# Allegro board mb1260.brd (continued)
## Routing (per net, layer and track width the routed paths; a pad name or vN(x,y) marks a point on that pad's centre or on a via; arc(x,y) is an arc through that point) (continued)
5V: length 96.6
  TOP w0.508: CN8.4 77.71,42.19 ; CN8.4 v4(80.09,41.35) ; CN8.4 77.71,40.51 ; 65.79,66.32 C17.2 ; C17.2 65.79,67.54 ; C17.2 65.14,66.93 ; P1.15 74.64,70.5 ; P1.15 73.77,71.36 ; P1.15 72.91,70.5 ; P1.15 73.77,69.64 ; 70.91,72.5 P1.6 ; P1.6 71.77,73.36 ; P1.6 72.64,72.5 ; P1.6 71.77,71.64 ; L3.1 v4(20.19,27.56) 17.17,30.58 CN12.5 ; 64.76,67.14 U4.6 64.32,66.59 ; 77.71,35.43 CN8.8 ; CN8.8 77.71,37.11 ; CN8.8 v4(80.09,36.27) ; 64.32,70.57 U4.1 64.76,70.02 ; 42.42,93.6 v4(42.42,94.61) ; CN8.10 77.71,34.57 ; CN8.10 77.71,32.89 ; CN8.10 v4(80.09,33.73) ; v4(44.43,94.72) 44.81,94.34 D1.1 ; CN8.6 77.71,39.65 ; CN8.6 v4(80.09,38.81) ; CN8.6 77.71,37.97 ; 65.43,69.47 65.91,69.47 ; 65.91,69.47 65.91,68.99 ; 65.91,69.47 65.91,69.95 ; CN8.2 v4(80.01,43.89) ; CN8.2 77.71,43.05 ; CN8.2 77.71,44.73 ; v4(36.13,13.36) U13.5 ; U14.5 v4(58.11,13.51)
  L4_SIG w0.508: P1.6 72.64,72.5 ; P1.6 71.77,71.64 ; P1.6 71.77,73.36 ; P1.6 70.91,72.5 ; 73.77,69.64 P1.15 ; P1.15 73.77,71.36 ; P1.15 74.64,70.5 ; P1.15 72.91,70.5
  BOTTOM w0.508: v4(42.42,94.61) 42.53,94.72 v4(44.43,94.72) 45.48,94.72 46.23,93.98 46.23,79.88 50.42,75.69 50.42,73.03 52.7,70.74 55.88,70.74 56.9,69.72 58.29,69.72 58.93,70.36 64.64,70.36 65.53,69.47 v4(65.53,68.71)
  vias: v4(65.53,67.94) v4(66.29,68.71) v4(66.29,67.94) v4(79.32,45.85) v4(79.35,45.01)
5V_ST_LINK: length 44.4
  TOP w0.508: U1.7 64.9,78.74 ; U1.6 C5.2 ; C5.2 65.41,76.99 ; C5.2 65.41,77.95 ; SB3.2 65.5,79.28
  TOP w1.016: CN8.1 70.79,43.89 69.88,44.81 69.88,76.43 67.56,78.74 66.42,78.74
5V_USB_FS: length 42.4
  TOP w0.508: D3.1 70.16,36.2 ; D3.1 68.94,36.2 ; D3.1 69.55,36.81 ; D3.1 69.55,35.58
  L4_SIG w1.016: 68.84,34.22 66.32,31.7 66.32,26.95 64.52,25.15 63.22,25.15 59.94,21.87 59.94,12.32 57.58,9.96 50.98,9.96 50.42,9.4 49.2,9.4
  BOTTOM w0.508: 48.12,9.31 R99.2 47.29,8.51
  vias: v1(68.78,35.15) v1(69.42,35.13) v4(47.62,10.41) v4(48.39,10.41)
5V_USB_HS: length 109
  TOP w0.254: U15.1 27.55,6.59 27.2,6.25 v4(27.03,6.25)
  TOP w0.508: U13.1 36.2,9.41 C78.1 35.56,7.11 v1(35.31,7.11) ; v1(40.69,10.74) 40.69,12.4 41.12,12.83 R74.2 ; D5.1 69.55,42.01 ; D5.1 70.38,41.4 v4(70.43,41.35) CN8.3 ; D5.1 68.94,41.4
  L4_SIG w1.016: 28.07,6.76 29.57,6.76 31.04,8.23 37.52,8.23 39.29,6.45 46.32,6.45 61.01,6.45 62,5.46 62,4.27 62.84,3.43 64.64,3.43 66.75,5.54 66.75,23.29 72.64,29.18 72.64,41.02 72.06,41.61
  BOTTOM w0.254: v4(27.03,6.25) 27.03,5.79 27.3,5.51 CN19.1
  BOTTOM w0.508: 28.07,7.11 R98.2 v1(35.31,7.11) 36.47,7.11 40.11,10.74 v1(40.69,10.74)
  vias: v4(26.42,6.68) v4(70.46,42.09)
5V_USB_ST_LINK: length 103
  TOP w0.381: 54.99,90.95 53.76,92.18 CN1.1 ; SB3.1 65.52,81.14
  TOP w0.508: v4(52.5,82.96) 52.48,82.93 R11.1 ; 69.55,32.71 D2.1 ; D2.1 69.55,33.93 ; D2.1 68.94,33.32 ; D2.1 70.16,33.32 ; 55.78,78.61 R20.2 ; R20.2 56.26,79.1 ; R20.2 56.74,78.61 ; 58.67,83.06 R2.2 57.55,91.71 v4(56.77,90.93) 56.75,90.95 54.99,90.95 ; U1.1 58.08,80.49 ; U1.1 59.17,80.01 ; U1.1 56.99,80.01 ; U1.1 58.08,79.53 ; 56.99,78.74 U1.2 ; U1.2 59.17,78.74 ; U1.2 58.08,79.22 ; C3.2 58.17,82.14 ; C3.2 58.81,81.53 ; C3.2 58.17,80.92 ; R15.2 60.45,82.02 ; R15.2 60.45,81.05 ; R15.2 59.97,81.53 ; U21.5 v4(52.83,86.23)
  L4_SIG w0.508: v4(52.83,86.23) 52.5,85.9 v4(52.5,82.96)
  BOTTOM w0.508: v4(52.5,82.96) v4(58.09,82.96)
  BOTTOM w1.016: 67.69,33.4 67.56,33.53 67.56,45.09 77.85,55.37 77.85,78.74 73.79,82.8 67.69,82.8 66.8,81.92 v4(66.17,81.92)
  vias: v4(65.15,81.92) v4(68.71,32.51) v4(68.71,31.75)
GND: length 438.4
  TOP w0.127: U7.F7 15.96,60.6 v3(15.78,60.6) U7.E7 ; U7.A4 v3(13.46,58.78) 13.46,58.6 U7.A3 ; U7.H9 v3(17.28,61.6) ; U7.C1 v3(14.46,57.28) ; U7.E8 v3(15.78,61.1) ; U7.E2 v3(15.78,57.78) ; U7.A5 v3(13.46,59.6) ; U7.D6 v3(14.96,60.1) ; U7.G5 v3(16.78,59.6) ; U7.A1 v3(13.46,57.28)
  TOP w0.152: U20.11 42.49,62.28 43.05,61.72 43.05,61.21
  TOP w0.254: U8.G10 v2(37.44,47.46) ; U8.G9 v2(36.79,47.46) 36.47,47.78 U8.F9 ; v4(42.42,76.45) 42.05,76.08 U2.8 ; U15.8 27.55,8.57 v4(27.41,8.71) ; U8.F2 U8.G2 v2(32.24,46.81) ; v2(30.18,43.74) 31.12,43.74 U8.M1 ; U8.F7 v2(34.84,48.11) 34.51,47.79 U8.F6 ; U8.D9 v2(36.79,49.41) ; U8.K9 v2(36.79,44.86) ; U8.H8 v2(35.49,46.16) ; U8.K6 34.51,45.18 v2(34.84,44.86) U8.K7 ; U8.F10 37.36,48.03 v2(37.52,48.03) ; v4(51.11,79.25) 50.95,79.08 U2.35 ; U8.H9 v2(36.79,46.16) ; U8.G12 38.41,47.14 38.25,47.3 38.25,47.62 U8.F12 v2(38.74,48.11) ; U15.5 29.05,8.22 v4(29.46,8.64) ; U8.G8 v2(35.49,47.46) ; v2(30.19,42.97) 30.27,42.97 30.51,43.21 31.24,43.21 U8.N1 ; U2.20 46.34,73.67 v4(46.23,73.79) ; U8.M8 v2(35.49,43.56) ; U2.23 47.84,73.32 v4(47.5,73.66) ; U10.E6 45.14,29.03 v2(45.09,29.03) ; U8.D5 v2(33.54,49.41) ; U10.H1 v2(43.7,32.89) ; U8.H6 34.51,46.48 v2(34.84,46.16) U8.H7 ; U8.K8 v2(35.49,44.86) ; U8.D8 v2(35.49,49.41) 35.16,49.09 U8.D7 ; U8.J10 v2(37.44,45.51) ; U8.J6 34.51,45.83 v2(34.84,45.51) U8.J7 ; U8.J9 v2(36.79,45.51) ; U8.H10 v2(37.44,46.16) 37.77,46.48 U8.H12 ; U2.47 v4(43.34,79.85) ; U8.J8 v2(35.49,45.51) ; U8.F8 v2(35.49,48.11) ; U8.G6 34.51,47.14 v2(34.84,47.46) U8.G7 ; U8.K10 v2(37.44,44.86)
  TOP w0.305: U8.M9 36.47,43.88 v2(36.81,44.22)
  TOP w0.381: CN1.5 51.16,92.18 v4(50.67,91.69) ; v4(51.56,14.49) 51.17,14.1 50.42,14.1 50.04,14.48 ; U10.D1 46.68,33.57 v2(46.68,33.62) ; 50.04,14.48 49.28,14.48 ; 50.04,14.48 50.04,14.49 ; SB6.1 v4(36.91,73.58) ; C46.1 v4(26.29,51.44) ; v4(26.92,44.07) 26.92,44.7 C53.1
  TOP w0.508: 45.76,8.18 T2.2 ; T2.2 v4(44.7,8.7) ; T2.2 46.54,8.7 ; T2.2 45.76,9.22 ; CN19.6 26.32,5.46 ; CN19.6 25.59,4.46 ; CN19.6 27.06,4.46 ; CN19.6 26.32,3.46 ; U3.2 v4(65.02,73.53) ; 6.97,27.94 7.75,27.94 ; 7.75,27.94 7.75,28.78 ; 7.75,27.94 7.75,27.1 ; 54.96,93.8 CN1.8 55.91,92.85 ; U9.1 5.65,41.63 ; U9.1 4.94,42.74 ; U9.1 4.94,40.52 ; U9.1 4.23,41.63 ; R8.1 v4(50.93,82.93) ; 38.09,93.77 LD4.1 ; LD4.1 v4(39.35,94.72) ; LD4.1 38.09,95.67 ; 49.81,89.42 R9.1 ; R9.1 50.78,89.42 ; R9.1 v4(50.29,88.52) ; 57.68,71.25 C11.1 ; C11.1 58.9,71.25 ; C11.1 58.29,70.6 ; C37.1 29.72,55.22 29.31,55.63 29.31,55.83 v4(29.26,55.88) ; 49.59,4.46 CN18.6 ; CN18.6 51.06,4.46 ; CN18.6 50.33,5.46 ; CN18.6 50.33,3.46 ; C26.2 22.37,63.12 ; C26.2 21.72,63.73 ; C26.2 21.29,63.55 v4(21.29,64.03) ; v4(11.3,52.83) 11.86,53.39 C41.2 ; C57.1 3.32,43.43 ; C57.1 2.1,43.43 ; C57.1 2.71,42.79 ; C9.1 67.83,74.42 ; C9.1 67.18,73.81 ; C9.1 v4(67.18,75.44) ; v4(67.43,67.89) 67.43,67.86 67.31,67.74 C17.1 v4(67.31,65.91) ; v4(28.5,55.88) 28.41,55.97 28.34,55.97 28.32,55.99 C36.1 ; 36.04,37.72 36.88,37.72 v4(36.98,37.82) ; 49.01,92.85 CN1.9 ; CN1.9 49.96,93.8 ; CN1.9 49.96,91.9 ; U11.1 5.65,30.25 ; U11.1 4.23,30.25 ; U11.1 4.94,29.15 ; U11.1 4.94,31.36 ; 58.08,75.72 U1.4 ; U1.4 v4(56.52,76.2) ; U1.4 59.17,76.2 ; U1.4 58.08,76.68 ; C4.1 v4(37.49,78.36) ; CN18.7 55.61,4.46 ; CN18.7 54.88,3.46 ; CN18.7 54.88,5.46 ; CN18.7 54.14,4.46 ; C15.1 59.56,69.47 v4(59.69,69.6) ; C64.2 v4(23.62,36.83) ; C64.2 25.15,37.08 25.15,37.85 v4(24.89,38.1) ; C64.2 25.73,36.83 ; C64.2 24.89,35.86 ; C64.2 24.89,37.8 ; v4(36.96,35.43) C66.2 ; C66.2 38.23,34.29 38.25,34.26 v4(38.25,34.16) ; C66.2 38.23,36.27 ; C66.2 39.19,35.43 ; v4(23.9,61.21) 23.24,60.55 R31.2 R33.2 ; P2.11 71.36,20.54 ; P2.11 72.32,19.57 ; P2.11 71.36,18.61 ; P2.11 70.39,19.57 ; CN14.7 4.24,20.7 ; CN14.7 3.38,19.84 ; CN14.7 3.38,21.57 ; CN14.7 2.51,20.7 ; 32.75,2.44 CN19.8 33.65,1.28 ; R36.1 32.55,58.2 32.8,58.2 32.8,58.19 v4(32.81,58.19) ; R36.1 31.52,57.66 ; R36.1 32,58.14 ; C22.2 v4(16,67.18) ; C71.1 45.49,25.12 v4(45.49,25.83) ; U4.2 v4(63.37,71.25) ; CN9.3 v4(54.55,57.78) ; C38.1 v4(35.69,55.75) ; v4(37.52,72.16) 37.52,71.93 38.2,71.25 R26.1 ; R76.1 v4(44.81,12.83) ; C78.2 v4(37.72,6.6) ; C78.2 38.37,7.75 ; C78.2 37.08,8.38 U13.2 ; C78.2 37.72,8.36 ; C16.1 60.96,68.96 v4(61.07,69.07) ; LD2.2 v4(41.02,95.63) ; LD2.2 40.41,94.36 ; LD2.2 41.63,94.36 ; C33.2 9.53,58.4 ; C33.2 9.04,57.91 ; C33.2 9.53,57.43 ; v4(32.08,38.23) 33.02,37.29 C65.2 33.02,36.2 32.38,35.56 v4(32.09,35.56) ; C34.2 41.78,57.78 v4(41.78,58.55) ; C34.2 41.02,57.78 v4(41.02,58.55) ; C34.2 40.44,57.4 ; C34.2 42.37,57.4 ; C34.2 41.4,58.24 ; C34.2 41.4,56.57 ; v1(45.09,41.3) 45.09,41.53 44.58,42.04 ; v4(48.08,38.94) 46.94,38.94 C58.1 46.69,39.32 47.04,39.67 48.06,39.67 v4(48.11,39.73) ; CN12.6 16.46,28.04 ; CN12.6 15.49,29.01 ; CN12.6 15.49,27.07 ; CN12.6 14.52,28.04 ; v1(42.74,38.18) 42.75,38.18 42.29,37.72 42.04,37.72 ; CN5.3 25.14,93.56 ; CN5.3 25.14,91.15 ; CN5.3 23.69,92.35 ; CN5.3 26.59,92.35 ; CN19.7 30.87,5.46 ; CN19.7 30.87,3.46 ; CN19.7 31.61,4.46 ; CN19.7 30.14,4.46 ; C3.1 56.64,82.14 ; C3.1 56.26,81.15 v4(55.5,81.15) ; C3.1 55.99,81.53 ; C3.1 56.26,81.92 v4(55.5,81.92) ; U6.4 32.77,61.34 32.51,61.09 v4(32.51,61.07) ; U6.4 32.77,62.63 ; U6.4 32.28,61.97 ; U6.4 33.25,61.97 ; 44.83,83.95 v4(43.94,83.95) ; C47.1 27,49.96 v4(26.21,49.96) ; C77.2 60.21,7.87 ; C77.2 59.56,7.26 ; C77.2 59.05,8.38 U14.2 ; CN12.7 15.49,26.47 ; CN12.7 16.46,25.5 ; CN12.7 14.52,25.5 ; C50.1 v4(60.33,48.77) ; C50.1 61.34,49.42 ; C50.1 61.95,48.77 ; v4(23.88,40.13) 23.88,40.51 C93.1 ; CN2.3 66.28,94.39 ; CN2.3 64.55,94.39 ; CN2.3 65.42,93.53 ; CN2.3 65.42,95.26 ; v4(67.39,68.71) 67.39,69.01 C14.1 ; CN1.7 49.76,95.55 ; CN1.7 48.16,95.55 ; CN1.7 48.96,94.39 ; C48.1 25.25,50.04 ; C48.1 24.77,50.52 ; C48.1 v4(24.03,50.04) ; CN3.2 68.2,84.57 ; CN3.2 66.27,84.57 ; CN3.2 67.24,85.53 ; CN3.2 67.24,83.6 ; v4(44.3,66.9) 44.45,66.75 C92.2 ; T1.2 v4(41.83,7.82) ; C54.2 48.54,45.34 v4(48.67,45.47) ; C7.1 v4(37.49,75.82) ; 63.75,41.3 CN11.7 ; CN11.7 64.72,42.26 ; CN11.7 63.75,43.23 ; CN11.7 62.78,42.26 ; 68.82,18.61 P2.5 ; P2.5 68.82,20.54 ; P2.5 69.78,19.57 ; P2.5 67.85,19.57 ; C6.1 v4(37.49,77.09) ; C23.2 v4(17.53,66.93) ; CN4.3 11.32,93.56 ; CN4.3 11.32,91.15 ; CN4.3 9.87,92.35 ; CN4.3 12.77,92.35 ; C19.1 v4(12.06,67.18) ; CN9.5 v4(54.48,55.24) ; 48.45,2.44 CN18.9 47.55,1.28 ; 59.69,71.02 C12.1 ; C12.1 60.17,71.5 ; C12.1 59.21,71.5 ; C40.1 v4(43.31,55.88) ; C40.1 43.79,54.99 ; C40.1 42.82,54.99 ; 53.46,94.39 CN1.10 54.41,95.55 ; v4(67.31,76.58) 66.93,76.2 R22.2 ; C52.1 44.65,46.66 v4(45.47,46.66) ; C14.1 66.93,69.95 ; C14.1 67.41,69.47 ; 2.71,31.61 C68.1 ; C68.1 3.55,32.38 ; C68.1 1.87,32.38 ; 11.38,53.49 C41.2 ; C41.2 12.34,53.49 ; R16.1 36.96,13.67 v4(37.49,14.2) ; R17.1 v4(37.49,80.52) ; 57.65,1.28 CN18.8 56.75,2.44 ; R22.2 66.42,75.72 ; R22.2 66.42,76.68 ; 43.05,61.21 v4(43.05,60.45) ; 55.96,94.39 CN1.6 ; CN1.6 56.76,95.55 ; CN1.6 55.16,95.55 ; C45.1 v4(45.21,52.2) ; C35.1 v4(9.02,53.47) ; v4(32.08,39.12) 31.75,39.12 C60.1 ; C55.1 v4(21.59,44.07) ; X3.2 26.04,43.51 v4(26.04,42.93) ; R54.2 48.21,44.2 v4(48.31,44.09) ; 24.28,46.99 C51.1 ; C51.1 25.48,46.99 ; C51.1 24.77,46.51 ; C21.2 v4(14.73,67.18) ; C10.1 v4(67.82,72.9) ; L5.1 31.11,23.22 ; L5.1 v4(31.11,21.46) ; L5.1 31.76,22.61 ; 8.37,59.18 C31.1 9.02,58.57 ; 48.01,83.95 v4(48.01,84.84) ; C42.2 12.34,52.7 v4(12.33,52.7) ; C20.2 v4(13.46,67.18) ; C39.1 v4(39.5,56.01) ; R19.1 v4(37.49,79.5) ; C63.1 48.82,37.59 v4(48.87,37.54) ; C24.2 v4(18.8,67.18) ; 42.67,83.95 43.16,83.95 ; 42.67,83.95 42.67,84.43 ; 42.67,83.95 v4(41.78,83.95) ; 38.51,62.01 38.99,62.01 ; 38.99,62.01 38.99,62.67 ; 38.99,62.01 v4(38.99,60.96) ; C59.1 v4(26.37,38.61) ; 51.46,94.39 CN1.11 50.51,95.55 ; R75.2 v4(43.77,12.83) ; C13.1 v4(36.2,72.14) ; 23.55,1.28 CN19.9 24.45,2.44 ; C28.2 v4(20.95,62.36) ; U21.2 v4(52.83,88.65) ; C43.1 v4(17.32,51.94) ; v4(26.19,52.64) 26.21,52.64 26.28,52.58 C44.1 ; R61.1 v4(26.37,39.62) ; C5.1 v4(67.31,77.47) ; R37.1 v4(34.54,58.42) ; v4(48.01,48.64) C49.1 ; C8.1 v4(57.2,74.55) ; C29.1 8.31,60.58
  L4_SIG w0.508: 55.16,95.55 CN1.6 ; CN1.6 56.76,95.55 ; CN1.6 55.96,94.39 ; 64.55,94.39 CN2.3 ; CN2.3 66.28,94.39 ; CN2.3 65.42,93.53 ; CN19.7 30.87,5.46 ; CN19.7 30.14,4.46 ; CN19.7 30.87,3.46 ; CN19.7 31.61,4.46 ; P2.5 69.78,19.57 ; P2.5 67.85,19.57 ; P2.5 68.82,20.54 ; 25.59,4.46 CN19.6 ; CN19.6 27.06,4.46 ; CN19.6 26.32,3.46 ; CN18.7 54.88,5.46 ; CN18.7 55.61,4.46 ; CN18.7 54.14,4.46 ; CN18.7 54.88,3.46 ; 54.01,92.85 CN1.8 ; CN1.8 54.96,93.8 ; CN1.8 54.96,91.9 ; CN1.8 55.91,92.85 ; 48.45,2.44 CN18.9 47.55,1.28 ; CN1.9 49.96,93.8 ; CN1.9 49.96,91.9 ; CN1.9 50.91,92.85 ; CN1.9 49.01,92.85 ; CN14.7 3.38,21.57 ; CN14.7 2.51,20.7 ; CN14.7 4.24,20.7 ; CN14.7 3.38,19.84 ; P2.11 71.36,20.54 ; P2.11 70.39,19.57 ; P2.11 72.32,19.57 ; 33.65,1.28 CN19.8 32.75,2.44 ; 24.45,2.44 CN19.9 23.55,1.28 ; CN18.6 50.33,5.46 ; CN18.6 51.06,4.46 ; CN18.6 50.33,3.46 ; CN18.6 49.59,4.46 ; CN3.2 68.2,84.57 ; CN3.2 67.24,85.53 ; CN3.2 66.27,84.57 ; CN3.2 67.24,83.6 ; 56.75,2.44 CN18.8 57.65,1.28 ; CN1.7 49.76,95.55 ; CN1.7 48.96,94.39 ; CN1.7 48.16,95.55
  BOTTOM w0.178: v4(19.88,79.78) 20.07,79.96 CN16.3
  BOTTOM w0.203: CN16.1 21.98,80.76 21.42,81.32 v4(20.34,81.32) ; v4(26.54,79.88) 25.66,80.76 CN16.10 ; CN16.6 24.63,79.16 v4(24.15,78.68)
  BOTTOM w0.254: v4(50.25,18.61) 50.1,18.61 49.53,18.03 CN17.27 ; U17.5 v4(2.51,86.57) ; U16.5 18.03,86.57 17.63,86.17 v4(17.63,85.57) ; v4(56.21,8.28) 55.93,8 U23.2 ; U18.5 v4(17.72,71.72) ; U19.5 3.17,71.72 2.87,71.42 v4(2.87,70.74) ; CN17.1 v4(41.73,16.63)
  BOTTOM w0.381: v4(53.9,5.26) 53.9,5.26 CN18.5 53.9,3.12 ; 29.9,3.12 CN19.5
  BOTTOM w0.508: B2.2 73.83,31.33 ; B2.2 73.75,30.57 v4(73.75,30.01) ; B2.2 72.99,32.04 ; B2.2 72.99,30.62 ; B2.2 72.15,31.33 ; 17.88,80.54 R21.1 18.36,80.05 ; 54.96,91.9 CN1.8 ; CN1.8 54.96,93.8 ; CN1.8 55.91,92.85 ; CN1.8 54.01,92.85 ; v4(48.77,78.49) 49.02,78.23 C81.1 ; C2.2 17.85,82.19 ; 57.65,1.28 CN18.8 56.75,2.44 ; C82.1 43.31,77.06 ; C82.1 42.55,76.58 v4(42.42,76.45) ; C82.1 43.79,76.58 ; 48.45,2.44 CN18.9 47.55,1.28 ; v4(52.73,8.28) 52.2,8.81 U22.2 ; CN3.2 67.24,85.53 ; CN3.2 68.2,84.57 ; CN3.2 66.27,84.57 ; B2.4 v4(79.25,31.33) ; B2.4 77,31.33 ; B2.4 77.84,30.62 ; B2.4 77.84,32.04 ; 2.51,20.7 CN14.7 ; CN14.7 3.38,21.57 ; CN14.7 3.38,19.84 ; v4(80.09,35.03) 80.09,35.23 79.5,35.81 C87.1 ; CN1.7 49.76,95.55 ; CN1.7 48.96,94.39 ; CN1.7 48.16,95.55 ; 47.24,72.03 C83.1 ; C83.1 47.24,73.41 v4(47.5,73.66) ; C83.1 46.76,72.52 ; 77.37,42.04 R89.1 ; R89.1 77.85,41.55 ; R89.1 79.53,42.04 v4(80.09,42.6) ; 25.59,4.46 CN19.6 26.32,3.46 ; 65.42,93.53 CN2.3 ; CN2.3 66.28,94.39 ; CN2.3 65.42,95.26 ; CN2.3 64.55,94.39 ; 15.49,26.47 CN12.7 15.49,24.53 ; 8.26,87.61 C80.2 8.74,87.12 ; P2.11 72.32,19.57 ; P2.11 71.36,18.61 ; P2.11 70.39,19.57 ; P2.11 71.36,20.54 ; 55.96,94.39 CN1.6 ; CN1.6 56.76,95.55 ; CN1.6 55.16,95.55 ; SB2.2 23.65,73.66 v4(24.13,73.66) ; CN19.7 30.87,5.46 ; CN19.7 30.87,3.46 ; CN19.7 31.61,4.46 ; 48.14,5.98 U24.2 47.24,6.86 ; CN18.7 54.88,5.46 ; CN18.7 55.61,4.46 ; CN18.7 54.88,3.46 ; v4(75.18,43.94) 75.44,43.69 75.44,43.05 ; 32.75,2.44 CN19.8 33.65,1.28 ; 50.33,3.46 CN18.6 49.59,4.46 ; R18.1 v4(22.5,76.19) ; CN1.9 49.96,93.8 ; CN1.9 49.01,92.85 ; CN1.9 50.91,92.85 ; CN1.9 49.96,91.9 ; U18.2 19.47,71.26 v4(20.18,70.55) ; U19.2 4.62,71.2 v1(5.33,70.48) ; LD6.2 v4(2.29,50.29) ; LD6.2 2.29,48.79 ; LD6.2 1.64,49.4 ; P2.5 69.78,19.57 ; P2.5 67.85,19.57 ; P2.5 68.82,18.61 ; P2.5 68.82,20.54 ; 23.08,72.26 v4(24,72.26) ; 15.49,29.01 CN12.6 15.49,27.07 ; 24.45,2.44 CN19.9 23.55,1.28 ; LD1.2 v4(0.89,47.12) ; v4(2.29,52.7) LD5.2 2.29,51.05 ; 8.26,72.26 v4(9.27,72.26) ; C79.2 v4(24.31,87.12)
  vias: v1(5.33,87.81) v1(5.33,85.39) v1(5.33,72.97) v1(7.04,86.64) v1(7.04,71.78) v1(20.14,87.81) v1(20.17,85.37) v1(21.89,86.64) v1(27.1,71.94) v1(28.57,74.3) v2(29.16,47.5) v2(29.34,48.97) v2(39.92,40.52) v2(41.18,40.58) v2(41.5,49.61) v4(0.89,87.5) v4(0.89,79.76) v4(0.89,72.04) v4(0.89,64.31) v4(0.89,56.59) v4(0.89,41.14) v4(0.89,25.69) v4(0.89,17.96) v4(1.19,31.42) v4(2.13,30.45) v4(2.13,29.69) v4(2.29,41.91) v4(2.29,40.89) v4(2.95,30.45) v4(2.95,29.69) v4(3.17,41.91) v4(3.17,40.89) v4(5.33,52.83) v4(7.92,61.34) v4(7.92,58.42) v4(8.32,88.16) v4(8.38,67.44) v4(8.43,57.84) v4(10.95,89.11) v4(13.34,69.22) v4(13.97,39.24) v4(14.1,34.67) v4(15.75,75.46) v4(16.51,48.77) v4(16.64,44.58) v4(16.76,9.02) v4(17.02,37.97) v4(17.42,82.12) v4(17.47,81.17) v4(20.07,75.11) v4(20.17,72.97) v4(21.31,50.34) v4(21.34,47.27) v4(21.87,71.81) v4(22.1,0.89) v4(22.23,48.74) v4(23.5,30.86) v4(24.03,47.04) v4(24.05,64.9) v4(27.15,67.94) v4(27.69,61.34) v4(30.73,84.96) v4(31.11,17.4) v4(32.84,6.35) v4(33.4,78.61) v4(33.4,76.07) v4(33.53,13.21) v4(33.63,15.72) v4(34.42,11.05) v4(35.43,79.63) v4(35.43,74.55) v4(36.17,4.7) v4(36.2,3.43) v4(36.2,0.89) v4(36.27,18.31) v4(36.93,87.86) v4(36.91,25.5) v4(37.85,17.4) v4(38.89,30.4) v4(40.13,87.38) v4(40.6,0.89) v4(42.8,87.88) v4(42.8,73.79) v4(42.85,5.26) v4(44.45,86.49) v4(44.72,89.11) v4(44.83,73.79) v4(45.59,77.72) v4(45.59,76.45) v4(46.48,4.83) v4(47.12,0.89) v4(47.37,86.49) v4(47.5,67.44) v4(48.01,79.63) v4(48.13,4.06) v4(48.72,75.46) v4(53.09,2.92) v4(53.16,96.11) v4(53.34,67.44) v4(53.52,45.09) v4(53.75,15.93) v4(54.36,34.34) v4(54.38,25.93) v4(54.36,18.62) v4(54.61,49.66) v4(54.74,71.5) v4(54.74,13.72) v4(54.86,74.8) v4(56.21,38.84) v4(56.44,22.56) v4(56.44,16.51) v4(57.23,71.37) v4(57.23,70.61) v4(57.91,5.08) v4(58.17,0.89) v4(58.8,52.58) v4(59.82,46.74) v4(60.45,69.47) v4(60.58,84.33) v4(60.55,43.51) v4(60.78,8.2) v4(62.48,69.09) v4(62.48,68.07) v4(63.37,68.58) v4(64.26,69.09) v4(64.26,68.07) v4(67.39,0.89) v4(68.2,6.48) v4(69.42,43.48) v4(70.05,89.11) v4(71.37,5.21) v4(73.91,48.51) v4(74.55,84.33) v4(76.71,21.84) v4(77.34,51.31) v4(78.49,89.11) v4(78.49,0.89) v4(80.01,32.38) v4(80.11,87.49) v4(80.11,79.76) v4(80.11,72.04) v4(80.11,64.31) v4(80.11,56.59) v4(80.11,48.86) v4(80.11,25.69) v4(80.11,17.96) v4(80.11,10.24) v4(80.11,2.51)
V12_OTGPHY: length 6.9
  TOP w0.127: U8.J14 40.03,46.15 40.62,46.15 40.75,46.02 41.08,46.02 41.15,46.09 45.35,46.09 C54.1
VDD: length 69.8
  TOP w0.254: U8.C7 35.16,49.73 v2(35.49,50.06) U8.C8 ; U8.C5 v2(33.54,50.06) ; v2(36.79,42.91) 36.46,43.23 U8.N9 ; v2(35.49,42.91) 35.49,42.92 35.8,43.23 U8.N8 ; U8.C1 31.22,49.77 30.97,49.77 30.83,49.91 v2(30.63,49.91) ; U8.N10 37.11,43.23 36.79,43.55 v2(36.79,43.55) ; U8.J12 v2(38.74,45.51) 39.06,45.83 U8.J13 ; U8.F3 U8.G3 v2(32.89,46.81) ; U8.C9 v2(36.79,50.06) ; v2(39.39,46.16) U8.H13 U8.G13 ; U8.K4 33.24,45.18 v2(33.6,45.55)
  TOP w0.381: v1(27.86,44.15) 27.86,44.63 C53.2 ; C47.2 28.73,49.91 28.94,49.7 v1(28.94,49.7) ; R68.1 49.66,17.4 49.1,16.84 SB15.1 ; C46.2 v1(28.93,51.44)
  TOP w0.508: v4(36.93,38.58) 36.78,38.73 C61.2 ; v4(41.94,39.57) 42.04,39.47 C62.2 ; v4(27.51,54.34) 27.87,53.98 28.32,53.98 ; v4(43.44,41.2) 43.44,41.25 43.56,41.38 C56.2 ; v1(38.13,39.25) 38.13,39.24 38.24,39.13 38.24,38.24 C66.1 ; 43.31,53.98 43.69,53.98 v4(44.45,53.21) ; 54.28,68.96 JP1.1 ; JP1.1 55.24,69.93 ; JP1.1 56.21,68.96 ; R70.1 50.16,16.52 v4(50.25,16.6) 50.25,17.32 R68.1 ; v1(42.8,46.66) 43.44,46.66 C52.2 ; 39.5,53.98 38.99,53.47 v4(38.99,53.33) ; 43.31,52.2 43.31,52.83 v4(43.56,53.09) ; v4(41.91,53.21) 41.91,54.1 C34.1 40.92,54.12 v4(40.92,53.23) ; 29.72,53.98 29.59,53.98 29.11,54.46 v4(29.06,54.46) ; v1(28.88,52.73) 28.35,52.73 C44.2 ; 35.69,53.98 35.69,53.59 v1(35.41,53.31) ; v4(33.91,33.4) 33.53,33.78 L1.1 ; R27.1 58.59,68.47 ; R27.1 56.98,68.47 ; R27.1 57.78,69.29
  L4_SIG w0.508: v4(43.44,41.2) 43.44,40.89 45.01,39.32 46.66,39.32 47.73,38.25 51.1,38.25 52.45,36.91 52.45,32.77 53.01,32.21 53.01,18.42 51.86,17.27 50.92,17.27 v4(50.25,16.6)
  BOTTOM w0.254: v4(50.25,16.6) 50.21,16.64 49.28,16.64 48.93,16.99 CN17.25
  vias: v4(52.96,69.85) v4(52.96,68.96) v4(53.72,69.85) v4(53.72,68.96)
VDDA: length 10.4
  TOP w0.254: U8.R1 31.09,41.93 30.07,40.91 30.07,38.76 C60.2
  TOP w0.508: L1.2 R62.2 29.86,36.21 C65.1 C60.2
VIN: length 9.2
  TOP w0.508: 9.53,27.1 C74.2 ; C74.2 9.53,28.78 ; C74.2 10.3,27.94 ; U11.3 9.54,31.36 ; U11.3 10.25,30.25 ; U11.3 9.54,29.15 ; 14.52,22.96 CN12.8 ; CN12.8 15.49,21.99 ; CN12.8 15.49,23.93 ; CN12.8 16.46,22.96
AIN_1: length 5
  TOP w0.127: U2.10 40.66,75.08 40.13,74.56 40.13,73.03 R25.2 R26.2
ARD_A0: length 34.9
  TOP w0.127: v2(31.88,41.05) 31.88,41.27 32.23,41.63 32.23,42.25 32.56,42.58 U8.P3
  L4_SIG w0.102: v2(31.88,41.05) 31.72,41.05 30.78,40.11 30.78,36.42 27.51,33.15 22.35,33.15 18.58,29.38 18.58,22.95 15.49,19.86 CN15.1
ARD_A1: length 138.7
  TOP w0.127: U8.N4 32.89,42.91 v2(32.89,42.91)
  L4_SIG w0.102: CN15.2 14.48,16.35 14.48,19.43 18.1,23.05 18.1,29.53 22.1,33.53 27.41,33.53 30.45,36.58 30.45,40.34 32.89,42.77 v2(32.89,42.91) ; v1(25.65,61.09) 24.38,59.82 24.38,55.24 18.03,48.9 v1(18.03,47.88)
  BOTTOM w0.127: v1(25.65,61.09) 27.81,63.25 40.01,63.25 42.55,65.79 46.74,65.79 48.39,64.14 68.45,64.14 68.96,64.64 68.96,65.53 ; CN15.2 15.49,15.37 14.1,16.76 14.1,33.66 14.99,34.54 16.51,34.54 18.67,36.7 18.67,41.66 18.03,42.29 v1(18.03,47.88)
ARD_A2: length 45.3
  TOP w0.127: U8.N5 34.19,43.56 v2(34.19,43.56)
  L4_SIG w0.102: v2(34.19,43.56) 33.8,43.94 33.01,43.94 32.39,44.56 32.09,44.56 31.37,43.84 31.37,42.54 29.54,40.71 29.54,38.81 26.04,35.31 21.72,35.31 19.68,33.27 19.68,31.75 17.4,29.46 17.4,22.86 14.1,19.56 14.1,15.14 14.79,14.44 14.79,13.5 CN15.3
ARD_A3: length 47
  TOP w0.127: v2(29.62,45.01) 29.62,44.93 29.97,44.58 30.74,44.58 30.78,44.53 U8.L1
  L4_SIG w0.102: CN15.4 14.43,11.32 14.43,14.25 13.79,14.88 13.79,33.1 15.11,34.42 16.51,34.42 21.46,39.37 21.67,39.37 21.72,39.42 24.56,39.42 25.53,40.39 25.53,40.51 26.29,41.27 26.8,41.27 27.59,42.06 27.59,42.65 28.02,43.08 28.02,43.67 29.25,44.91 29.29,44.91 29.39,45.01 v2(29.62,45.01)
ARD_A4: length 46.1
  TOP w0.127: v2(29.48,43.74) 29.51,43.74 29.98,44.2 31.6,44.2 U8.M2
  L4_SIG w0.102: v1(18.41,32.51) 18.41,33.27 19.56,34.42 19.56,35.38 21.51,37.34 25.91,37.34 27.69,39.12 27.69,40.87 28.5,41.68 28.5,42.27 28.93,42.7 28.93,43.2 29.46,43.74 v2(29.48,43.74)
  BOTTOM w0.127: 19.69,8.71 17.65,10.75 17.65,31.75 v1(18.41,32.51)
ARD_A5: length 49.8
  TOP w0.127: U8.M3 v2(32.24,43.56)
  L4_SIG w0.102: v2(32.24,43.56) 31.85,43.17 31.85,42.31 30.9,41.35 30.9,41.21 30.15,40.46 30.15,37.08 28.07,35 21.84,35 20.19,33.35 v1(20.19,32.64)
  BOTTOM w0.127: v1(20.19,32.64) 18.67,31.11 18.67,11.21 21.21,8.67 21.21,7.24 19.95,5.98 SB37.1
ARD_D0: length 63.5
  TOP w0.127: U8.R2 31.91,41.74 31.5,41.33 31.5,40.85 v2(31.86,40.49)
  L4_SIG w0.102: v1(32.61,18.67) 32.13,19.15 32.13,28.85 31.14,29.84 31.14,39.9 31.72,40.49 v2(31.86,40.49)
  BOTTOM w0.127: v1(32.61,18.67) 35.94,15.34 38.13,15.34 42.29,11.18 45.85,11.18 46.1,11.43 50.51,11.43 51.53,12.45 58.42,12.45 62.53,8.33 62.53,6.4 CN13.1
ARD_D1: length 61.7
  TOP w0.127: v2(31.83,39.95) 31.75,39.95 30.99,40.71 30.99,41.36 31.25,41.61 31.43,41.61 31.58,41.77 31.58,42.05 31.91,42.38 U8.P2
  L4_SIG w0.102: v2(31.83,39.95) 31.5,39.62 31.5,29.97 32.45,29.02 32.45,19.72 v1(32.66,19.51)
  BOTTOM w0.127: v1(32.66,19.51) 36.45,15.72 38.32,15.72 42.48,11.56 45.67,11.56 45.92,11.81 50.35,11.81 51.37,12.83 52.7,12.83 52.83,12.95 58.52,12.95 CN13.2
ARD_D2: length 60
  TOP w0.127: U8.P5 33.53,42.25 33.53,41.56 33.35,41.38 33.35,39.88 34.71,38.52 34.71,36.97 35.51,36.17 35.51,29.59 34.42,28.5 34.42,19.81 34.16,19.56 v1(34.16,19.55)
  BOTTOM w0.127: CN13.3 63.37,10.26 59.03,14.61 53.09,14.61 52.07,13.59 51.05,13.59 50.04,12.57 45.52,12.57 45.26,12.32 42.8,12.32 38.43,16.69 37.15,16.69 34.29,19.55 v1(34.16,19.55)
ARD_D3: length 95.1
  TOP w0.127: U8.B2 31.74,50.38 31.4,50.71 31.13,50.71 30.95,50.9 30.95,51.08 30.37,51.66 30.37,51.68 30.35,51.69 30.35,52.39 30.04,52.7 29.59,52.7 29.59,52.7 v2(29.56,52.7)
  BOTTOM w0.127: v2(29.56,52.7) 29.55,52.7 29.06,53.19 27.42,53.19 26.13,54.48 23.5,54.48 22.48,53.47 22.23,53.47 19.66,50.9 19.66,43.84 22.73,40.77 22.73,37.59 22.99,37.34 24.13,37.34 24.38,37.08 24.38,36.73 32.49,28.62 32.49,24.79 34.67,22.61 36.28,22.61 37.41,21.48 55.64,21.48 55.93,21.18 60.55,21.18 63.5,24.13 64.26,24.13 65.53,22.86 65.53,14.58 CN13.4
ARD_D4: length 76.3
  TOP w0.127: U8.G4 v2(33.54,46.81)
  L4_SIG w0.102: v2(33.54,46.81) 33.19,47.16 32.09,47.16 31.88,46.94 31.88,46.38 31.95,46.3 31.95,46.01 31.22,45.28 31.22,44.63 30.65,44.06 30.65,43.6 30.4,43.35 29.51,43.35 29.24,43.08 29.24,42.57 28.8,42.14 28.8,41.56 28.07,40.82 28.02,40.77 28.02,38.56 25.63,36.17 21.06,36.17 v1(20.19,35.31)
  BOTTOM w0.127: CN13.5 61.31,17.78 57.18,17.78 55.01,19.95 36.74,19.95 35.86,20.83 34.54,20.83 31.34,24.03 31.34,28.15 24.19,35.31 v1(20.19,35.31)
ARD_D5: length 119.3
  TOP w0.127: U8.R5 33.81,41.88 33.81,39.97 35.09,38.68 35.09,37.14 35.89,36.34 35.89,29.29 34.8,28.19 34.8,21.51 v1(35.03,21.29)
  L4_SIG w0.102: CN13.6 64.49,17.88 65.15,18.54 65.15,24.41 70.99,30.25 70.99,35.69 70.36,36.32 66.93,36.32 64.9,38.35 64.9,45.59 64.39,46.1 62.36,46.1 61.72,46.74 61.72,64.01 v1(63.12,65.41)
  BOTTOM w0.127: v1(63.12,65.41) 64.52,65.41 66.42,67.31 68.45,67.31 68.94,67.8 SB29.2 ; CN13.6 63.47,18.16 57.34,18.16 55.17,20.33 36.9,20.33 35.95,21.29 v1(35.03,21.29)
ARD_D6: length 92.9
  TOP w0.127: v2(31.93,52.32) 31.92,52.31 31.92,51.64 32.25,51.31 32.25,50.9 32.56,50.58 U8.B3
  BOTTOM w0.127: v2(31.93,52.32) 31.52,52.73 31.52,54.39 30.19,55.72 30.19,56.29 29.71,56.77 22.05,56.77 21.54,56.26 21.23,56.26 19.39,54.42 18.55,54.42 18.21,54.08 17.02,54.08 15.94,52.99 15.94,50.86 18.8,48.01 18.8,43.43 21.84,40.39 21.84,36.32 22.48,35.69 24.34,35.69 31.72,28.31 31.72,24.28 34.16,21.84 35.97,21.84 37.1,20.71 55.33,20.71 55.62,20.42 CN13.7
ARD_D7: length 82.6
  TOP w0.127: U8.A1 31.26,51.16 30.75,51.68 30.75,52.53 29.99,53.29 v2(29.51,53.29)
  BOTTOM w0.127: CN13.8 61.59,20.8 55.78,20.8 55.48,21.09 37.25,21.09 36.12,22.23 34.39,22.23 32.11,24.51 32.11,28.46 24.38,36.2 22.86,36.2 22.35,36.7 22.35,40.49 19.28,43.56 19.28,51.16 21.97,53.85 22.23,53.85 23.24,54.86 26.28,54.86 27.58,53.57 29.24,53.57 v2(29.51,53.29)
ARD_D8: length 79.8
  TOP w0.127: U8.B1 31.11,50.38 30.33,51.16 30.32,51.16 29.98,51.5 29.98,51.51 29.92,51.57 29.92,51.78 29.52,52.18 v2(29.52,52.17)
  BOTTOM w0.127: v2(29.52,52.17) 29.52,52.17 29.4,52.29 27.78,52.29 26.03,54.04 23.69,54.04 22.73,53.09 22.48,53.09 20.04,50.65 20.04,44.09 23.24,40.89 23.24,39.88 23.88,39.24 25.65,39.24 25.78,39.12 25.78,38.35 28.07,36.07 28.07,34.12 33.43,28.76 33.43,25.2 34.42,24.21 37.15,24.21 38.35,23 54.75,23 55.24,23.5 61.25,23.5 62.74,24.98 62.74,26.01 CN11.1
ARD_D9: length 41.5
  TOP w0.127: v2(38.09,44.21) U8.M11
  L4_SIG w0.102: v1(45.54,44.22) 45.34,44.01 42.35,44.01 41.66,44.7 40.05,44.7 39.1,45.65 39.1,45.65 38.89,45.86 38.59,45.86 38.09,45.36 v2(38.09,44.21)
  BOTTOM w0.127: v1(45.54,44.22) 46.03,44.7 51.64,44.7 55.83,40.51 59.82,40.51 60.47,39.86 61.36,39.86 61.98,39.24 61.98,34.29 62.87,33.4 64.52,33.4 65.02,32.89 65.02,30.84 CN11.2
ARD_D10: length 61.2
  TOP w0.127: U8.N2 31.58,42.9 30.83,42.9 30.48,42.55 30.47,42.55 30.41,42.48 30.04,42.48 v2(29.62,42.9)
  BOTTOM w0.127: CN11.3 62.36,30.71 62.36,25.14 61.09,23.88 54.99,23.88 54.5,23.38 38.6,23.38 38.58,23.39 38.58,23.39 37.38,24.59 34.75,24.59 33.88,25.45 33.88,28.84 28.57,34.15 28.57,38.13 27.84,38.86 27.84,41.27 29.46,42.9 v2(29.62,42.9)
ARD_D11: length 49.4
  TOP w0.127: U8.A6 34.51,51.48 34.69,51.66 34.69,51.96 v2(35.41,52.68)
  L4_SIG w0.102: v1(46.86,57.66) 47.8,56.72 47.8,54.05 49.43,52.43 49.43,46.41 54.36,41.48 59.6,41.48 61.85,39.23 61.85,35.69 62.89,34.64 CN11.4
  BOTTOM w0.127: v2(35.41,52.68) 35.64,52.91 36.7,52.91 37.21,53.42 37.21,53.85 38.73,55.37 43.78,55.37 46.07,57.66 v1(46.86,57.66)
ARD_D12: length 37.3
  TOP w0.102: v2(36.4,51.5) 36.46,51.43 U8.A9
  BOTTOM w0.127: CN11.5 64.9,38.33 64.9,40.39 64.26,41.02 61.21,41.02 59.49,42.75 57.96,42.75 50.33,50.38 40.37,50.38 39.95,50.8 38.48,50.8 38.18,51.1 36.79,51.1 v2(36.4,51.5)
ARD_D13: length 61.4
  TOP w0.127: U8.P4 32.91,42.27 32.91,42.27 v2(32.89,42.26) ; v1(59.82,39.88) 59.97,39.73 SB14.2 63.74,39.73 CN11.6
  L4_SIG w0.102: v1(35.31,25.53) 35.46,25.68 35.46,34.16 34.06,35.56 34.06,39.98 33.1,40.94 33.1,42.05 v2(32.89,42.26)
  BOTTOM w0.127: v1(59.82,39.88) 58.17,39.88 57.15,38.86 57.15,26.67 54.25,23.77 38.73,23.77 37.54,24.97 35.86,24.97 v1(35.31,25.53)
ARD_D14: length 197
  TOP w0.102: U8.J4 33.53,46.15 33.53,46.15 v2(33.56,46.18)
  TOP w0.127: v1(25.28,38.67) 25.27,38.67 R59.1
  L4_SIG w0.102: CN11.9 65.28,45.82 65.28,38.73 67.31,36.7 70.48,36.7 71.4,35.79 71.4,30.02 65.53,24.16 65.53,10.16 64.52,9.14 51.28,9.14 50.5,8.36 47.4,8.36 45.44,10.31 26.54,10.31 24.61,8.38 18.92,8.38 v1(17.78,9.53) ; v1(17.78,33.15) 19.05,34.42 19.05,35.31 21.72,37.97 24.05,37.97 24.74,38.67 v1(25.28,38.67) 25.46,38.67 25.91,39.12 26.92,39.12 27.38,39.57 27.38,40.99 28.19,41.81 28.19,42.4 28.63,42.83 28.63,43.42 29.41,44.2 30.47,44.2 30.96,44.69 30.96,46.1 31.62,46.76 31.62,47 32,47.37 33.53,47.37 33.91,46.99 33.91,46.63 33.56,46.28 v2(33.56,46.18)
  BOTTOM w0.127: v1(17.78,33.15) 17.02,32.38 17.02,10.29 v1(17.78,9.53) 17.78,9.02 18.03,8.76 ; CN11.9 62.74,47.34 62.48,47.6 62.48,50.67 62.87,51.05 69.34,51.05 75.44,57.15 75.44,70.48 74.42,71.5 70.23,71.5 67.94,73.79 67.94,79.46 SB27.1
ARD_D15: length 192.9
  TOP w0.102: U8.H4 v2(32.89,46.16)
  TOP w0.127: R60.1 28.5,40.77 28.65,40.92 28.65,41.4 29.19,41.94 v2(29.19,41.99)
  L4_SIG w0.102: CN11.10 64.16,49.88 65.66,48.39 65.66,39.12 67.69,37.08 70.61,37.08 71.75,35.94 71.75,29.62 65.91,23.77 65.91,10.03 64.64,8.76 51.36,8.76 50.62,8.03 47.76,8.03 47.74,8.05 47.19,8.05 45.31,9.93 45.27,9.93 44.85,9.93 44.85,9.93 26.77,9.93 24.84,8 21.46,8 19.3,5.84 v1(18.17,5.84) ; v2(32.89,46.16) 32.66,45.92 32.15,45.92 31.42,45.19 31.42,44.48 30.85,43.9 30.85,43.04 29.84,42.04 29.24,42.04 v2(29.19,41.99) 29.19,41.5 28.32,40.64 28.32,38.23 25.91,35.81 21.59,35.81 19.18,33.4 v1(19.18,32.51)
  BOTTOM w0.127: SB25.1 68.76,74.37 68.96,74.17 68.96,73.79 69.22,73.53 74.68,73.53 75.82,72.39 75.82,56.77 69.55,50.5 64.36,50.5 CN11.10 ; SB38.1 v1(18.17,5.84) 18.56,6.22 19.56,6.22 20.83,7.49 20.83,8.51 18.16,11.18 18.16,31.5 v1(19.18,32.51)
BLGND: length 12.6
  TOP w0.381: U12.3 v4(22.56,21.25)
  TOP w0.508: C75.1 24.77,12.19 v4(25.4,12.83) ; C70.1 v4(28.32,25.78) ; R69.1 v4(29.21,15.88) ; C69.1 v4(28.32,27.05) ; C76.1 v4(24.89,10.29) ; v4(28.7,24.51) C72.1 ; R67.1 v4(22.99,24) ; R66.1 v4(21.59,24.38) ; L5.2 v4(29.59,23.75) ; C67.2 v4(28.57,28.83) ; C73.1 v4(28.65,22.61)
  vias: v1(22.23,19.43) v1(22.23,18.41) v1(22.86,18.92) v1(23.62,19.43) v1(23.62,18.41)
BOOT0: length 9.1
  TOP w0.102: U8.D6 v2(34.19,49.41)
  TOP w0.127: R36.2 31.56,56.2 31.56,54.55 32.13,53.98 31.95,53.8 v2(31.95,53.24)
  BOTTOM w0.127: v2(31.95,53.24) 32.37,52.82 32.37,52.22 32.86,51.73 32.86,51.34 33.91,50.29 33.91,49.69 v2(34.19,49.41)
BYPASSREG: length 9.2
  TOP w0.127: R61.2 v1(28.85,40.28) ; U8.L4 33.21,44.54 33.51,44.83 v2(33.56,44.83)
  L4_SIG w0.102: v1(28.85,40.28) 28.91,40.34 28.91,40.79 29.57,41.45 29.77,41.45 31.05,42.74 31.05,43.82 32,44.77 32.48,44.77 32.79,44.45 33.15,44.45 33.53,44.83 v2(33.56,44.83)
CTP_INT: length 46.6
  TOP w0.102: v2(31.59,48.76) 32.24,48.76 U8.D3
  L4_SIG w0.102: v1(20.77,77.62) 21.45,76.94 23.52,76.94 25.65,74.8 25.65,62.61 26.16,62.1 26.16,60.71 24.77,59.31 24.77,54.61 23.75,53.59 v1(23.75,53.45)
  BOTTOM w0.127: v2(31.59,48.76) 30.54,48.76 29.12,50.18 27.06,50.18 26.68,50.56 25.92,50.56 23.75,52.72 v1(23.75,53.45) ; CN16.2 21.64,80.36 21.46,80.54 R21.2 19.38,78.63 20.39,77.62 v1(20.77,77.62)
CTP_RST: length 54.5
  TOP w0.127: U8.M13 v2(39.39,43.56)
  L4_SIG w0.102: v1(25.04,53.49) 25.04,53.92 26.16,55.04 26.16,56.84 27.1,57.78 27.1,61.93 26.04,62.99 26.04,75.18 24.86,76.36 24.86,78.7 v1(24.13,79.43)
  BOTTOM w0.127: v2(39.39,43.56) 39.39,43.68 39.78,44.07 39.78,44.32 39.76,44.34 39.76,44.36 39.54,44.57 39.53,44.57 39.52,44.58 39.32,44.58 39.14,44.75 39.14,45.69 37.75,47.09 34.57,47.09 34.04,47.62 33.52,47.62 32.99,48.15 32.99,48.35 31.82,49.53 31.82,50.1 31.32,50.6 29.92,50.6 29.57,50.94 27.88,50.94 26.67,52.15 25.98,52.15 25.04,53.08 v1(25.04,53.49) ; v1(24.13,79.43) 24.26,79.56 CN16.7 25.47,79.56 25.63,79.4 25.63,77.98 24.86,77.22 24.86,76.5 R18.2
CTP_SCL: length 77.7
  TOP w0.127: U8.F15 41.29,47.78 41.83,47.24 45.87,47.24 46.13,46.99 46.13,46.71 R52.2 47.12,47.24 50.67,47.24 v1(51.31,46.61)
  L4_SIG w0.102: v1(51.31,46.61) 51.64,46.94 51.64,70.74 52.96,72.06 52.96,73.91 52.25,74.63 45.14,74.63 42.7,77.06 41.43,77.06 38.48,80.01 37.08,80.01 36.6,80.49 22.7,80.49 v1(20.74,78.53)
  BOTTOM w0.127: CN16.5 22.01,79.16 21.59,78.74 20.95,78.74 v1(20.74,78.53)
CTP_SDA: length 86.7
  TOP w0.127: U8.M12 v2(38.74,43.56) ; v1(52.58,45.97) 51.94,45.97 48.9,42.93 47.24,42.93 R56.1 45.72,41.4 v1(45.72,41.27)
  L4_SIG w0.102: v2(38.74,43.56) 38.77,43.56 39.22,43.1 39.95,43.1 40.66,42.4 41.43,42.4 41.48,42.45 41.98,42.45 42.69,41.73 42.95,41.73 42.95,41.73 45.34,41.73 45.72,41.35 v1(45.72,41.27) ; v1(19.83,79.01) 22.23,81.41 38.1,81.41 41.76,77.75 43.28,77.75 45.09,75.95 51.94,75.95 53.72,74.17 53.72,71.63 52.32,70.23 52.32,46.23 v1(52.58,45.97)
  BOTTOM w0.127: v1(19.83,79.01) 20.13,79.31 21.46,79.31 21.72,79.56 CN16.4
DMIC_VDD: length 73.7
  TOP w0.508: v1(21.91,84.59) 21.92,84.58 v1(23.11,84.58) ; SB1.2 5.98,66.04 7.29,66.04 SB5.2 7.62,65.9 7.62,69.09 9.19,70.66 v1(9.19,71.25) 8.59,71.86 v1(8.59,84.2) v1(7.37,84.2)
  L4_SIG w0.508: v1(21.91,84.59) 20.24,86.26 10.64,86.26 v1(8.59,84.2) ; v1(21.59,69.47) 17.14,69.47 15.37,71.25 v1(9.19,71.25)
  BOTTOM w0.127: U18.1 21.05,71.32 21.82,70.56 22,70.56 ; U17.1 6.21,86.17 7.01,85.37 7.24,85.37 ; U19.1 6.21,71.32 6.97,70.56 7.15,70.56 ; U16.1 21.05,86.17 21.76,85.47
  BOTTOM w0.508: v1(7.37,84.2) 7.11,84.45 R86.2 ; 21.76,85.47 22.45,85.47 C79.1 23.24,85.95 23.24,84.71 v1(23.11,84.58) ; v1(8.59,84.2) 8.59,85.78 C80.1 7.52,85.37 7.24,85.37 ; R85.2 21.78,84.45 v1(21.91,84.59) ; v1(9.19,71.25) C85.1 8.26,71.22 7.59,70.56 7.15,70.56 ; v1(21.59,69.47) 22.48,69.47 23.08,70.07 C84.1 22.4,70.56 22,70.56
DMICCLK: length 74.5
  TOP w0.127: U7.C6 v3(14.46,59.78)
  L4_SIG w0.102: v1(18.26,87.98) 17.66,87.38 10.05,87.38 8.65,88.77 4.17,88.77 v1(3.78,88.39) v1(3.78,73.71) 4.98,72.52 7.82,72.52 8.32,73.01 v1(17.64,73.01)
  BOTTOM w0.127: v1(17.64,73.01) 18.38,73.01 19.21,72.17 U18.3 ; U17.3 4.37,87.02 3.78,87.6 v1(3.78,88.39) ; U19.3 4.37,72.17 3.78,72.76 v1(3.78,73.71) 2.67,73.71 2.18,73.23 2.18,69.57 10.81,60.95 11.49,60.95 12.45,59.99 13.44,59.99 13.59,60.15 14.09,60.15 v3(14.46,59.78) ; U16.3 19.21,87.02 v1(18.26,87.98)
DMICDAT1: length 54.7
  TOP w0.127: v3(14.15,62.09) 14.12,62.06 U7.B9
  BOTTOM w0.127: U17.4 6.23,87.02 6.99,87.78 v1(6.99,88.34) 7.39,88.75 9.47,88.75 10.72,87.5 10.72,77.83 14.15,74.4 20.89,74.4 v1(21.76,73.53) ; v1(21.76,73.53) 21.76,72.86 21.08,72.17 U18.4 ; v1(21.76,73.53) 22.1,73.53 22.74,72.9 24.29,72.9 25.1,72.09 25.1,69.14 23.98,68.02 15.7,68.02 15.37,67.69 15.37,63.31 v3(14.15,62.09)
DMICDAT2: length 48.8
  TOP w0.127: v3(13.49,61.94) 13.62,61.82 U7.A9
  L4_SIG w0.102: v1(21.97,88.34) 20.55,86.92 8.84,86.92 6.43,84.51 6.43,74.38 v1(7.43,73.38)
  BOTTOM w0.127: U19.4 6.23,72.17 v1(7.43,73.38) 10.29,73.38 12.65,71.02 12.65,62.78 v3(13.49,61.94) ; v1(21.97,88.34) 21.97,87.92 21.08,87.02 U16.4
E5V: length 200.4
  TOP w0.508: R58.2 v1(20.17,40.77) ; 68.94,38.86 D4.1 ; D4.1 70.16,38.86 ; D4.1 69.55,38.25 ; D4.1 69.55,39.47 ; C68.2 3.55,34.16 ; C68.2 2.71,34.94 ; C68.2 1.87,34.16 ; 7.24,35.45 U11.4 ; U11.4 5.38,36.55 ; U11.4 9.09,36.55 ; U11.4 7.24,37.66
  TOP w1.016: U11.2 7.24,33.02
  L4_SIG w0.508: v1(20.17,40.77) 20.17,39.85 17.37,37.06 14.58,37.06 11.91,34.39 2.26,34.39
  L4_SIG w1.016: 68.07,40.13 67.18,41.02 67.18,63.12 63.25,67.06 60.2,67.06 58.42,68.83 58.42,78.11 ; CN3.1 65.14,87.11 63.5,85.47 63.5,80.52 61.09,78.11 58.42,78.11 ; 58.42,78.11 50.8,78.11 49.97,78.93 49.97,79.95 48.64,81.28 42.36,81.28 36.8,86.84 26.9,86.84 23.62,83.57 21.13,83.57 18.68,81.11 18.68,77.88 22.99,73.58 22.99,62.23 20.45,59.69 20.45,53.21 17.91,50.67 13.21,50.67 7.75,45.21 7.75,40.69 5.13,38.07 2.79,38.07 1.75,37.03 1.75,36.47
  vias: v1(1.35,35.57) v1(1.37,34.9) v1(1.37,34.26) v1(2.04,35.55) v1(68.96,40.16) v1(69.6,40.13)
LCD-RS_A0: length 2
  TOP w0.127: R101.2 47.62,18.44 v1(47.75,18.57)
  BOTTOM w0.127: v1(47.75,18.57) 47.73,18.54 CN17.21
LCD_BL: length 66.7
  TOP w0.127: L7.1 v1(28.96,13.21) ; U8.L12 v2(38.74,44.21)
  L4_SIG w0.102: v2(38.74,44.21) 39.1,44.56 39.54,44.56 40.51,43.59 41.7,43.59 42.95,42.34 45.92,42.34 46.1,42.16 48.39,42.16 53.34,37.21 53.34,33.27 53.85,32.77 53.85,18.08 52.1,16.33 51.31,16.33 49.83,14.86 48.77,14.86 45.87,11.96 39.85,11.96 38.86,12.95 38.38,12.95 38.15,12.73 29.44,12.73 v1(28.96,13.21)
LCD_NE: length 54.3
  TOP w0.102: U8.C10 37.11,49.73 v2(37.44,49.4)
  TOP w0.127: v1(52.77,15.89) 52.63,15.75 51.18,15.75
  L4_SIG w0.102: v2(37.44,49.4) 37.44,49.4 37.44,49.3 37.87,48.87 37.87,47.17 40.03,45.01 42.04,45.01 42.34,44.7 45.82,44.7 47.68,42.85 48.77,42.85 54.86,36.75 54.86,27.03 55.22,26.67 55.22,16.9 55.09,16.78 53.64,16.78 52.76,15.89 v1(52.77,15.89)
  BOTTOM w0.127: v1(52.77,15.89) 52.22,15.34 48.23,15.34 48.03,15.13 CN17.22
LCD_PSRAM_D0: length 53.3
  TOP w0.127: v2(43.03,43.15) 43,43.18 41.3,43.18 41.15,43.33 40.72,43.33 40.7,43.36 40.69,43.36 40.5,43.55 40.05,43.55 U8.M14 ; v2(48.29,29.06) U10.B6
  L4_SIG w0.102: v2(48.29,29.06) 49.58,29.06 49.71,29.18 49.71,29.46 49.58,29.59 48.89,29.59 48.77,29.71 48.77,29.88 48.89,30 49.56,30 49.68,30.12 49.68,30.33 49.56,30.45 48.92,30.45 48.79,30.58 48.79,30.78 48.92,30.91 49.94,30.91 50.06,30.78 50.06,28.78 49.94,28.65 49.68,28.65 49.56,28.52 49.56,27.15 50.04,26.67 50.04,25.22 50.16,25.1 50.6,25.1 50.72,24.97 50.72,19.89 50.6,19.76 49.48,19.76 49.35,19.63 49.35,17.78 48.64,17.07 47.41,17.07 47.29,16.95 47.29,16.78 47.41,16.66 47.73,16.66 47.85,16.54 47.85,16.33 47.73,16.21 46.95,16.21 46.83,16.08 v1(46.83,16.05)
  BOTTOM w0.127: CN17.18 v1(46.83,16.05) ; v2(43.03,43.15) 42.95,43.23 42.95,44.53 43.08,44.65 43.36,44.65 43.48,44.53 43.48,42.62 44.86,40.8 49.4,36.26 49.4,31.88 49.28,31.75 49.15,31.75 49.02,31.62 49.02,31.37 49.15,31.24 49.28,31.24 49.4,31.11 49.4,30.86 49.3,30.76 49,30.76 48.87,30.63 48.87,29.64 v2(48.29,29.06)
LCD_PSRAM_D1: length 54.8
  TOP w0.127: v2(41.1,43.99) 41.1,44.1 41,44.2 40.05,44.2 U8.L14 ; U10.C5 v2(47.49,29.85)
  L4_SIG w0.102: v2(47.49,29.85) 47.73,29.85 47.85,29.72 47.85,28.8 47.98,28.68 49.12,28.68 49.25,28.55 49.25,27.28 49.25,27.28 49.25,27.03 49.25,26.9 49.73,26.42 49.73,24.87 49.86,24.74 50.27,24.74 50.39,24.61 50.39,24.41 50.27,24.28 49.35,24.28 49.25,24.18 49.25,23.98 49.35,23.88 50.25,23.88 50.37,23.76 50.37,23.59 50.25,23.47 49.35,23.47 49.25,23.37 49.25,23.16 49.35,23.06 50.22,23.06 50.34,22.94 50.34,22.78 50.22,22.66 49.35,22.66 49.25,22.56 49.25,22.35 49.35,22.25 50.32,22.25 50.42,22.15 50.42,20.19 50.29,20.07 49.17,20.07 49.05,19.94 49.05,19.28 48.87,19.1 48.26,19.1 48.13,18.97 48.13,18.8 48.26,18.67 48.9,18.67 49.02,18.54 49.02,17.88 48.9,17.75 48.67,17.75 48.54,17.88 48.54,18.01 48.41,18.14 47.24,18.14 47.12,18.26 47.12,18.54 47.37,18.8 47.37,19.05 47.27,19.15 47.12,19.15 46.67,18.71 v1(46.67,18.35)
  BOTTOM w0.127: v2(41.1,43.99) 41,43.89 40.74,43.89 40.64,43.99 40.64,44.91 40.36,45.19 40.06,45.19 39.93,45.31 39.93,45.67 39.8,45.8 39.52,45.8 39.4,45.67 39.4,44.96 39.52,44.83 40.18,44.83 40.31,44.7 40.31,44.2 40.06,43.94 40.06,43.66 40.18,43.54 41.25,43.54 41.48,43.31 41.66,42.93 42.47,41.21 42.47,40.87 43.02,40.32 43.7,40.32 48.26,35.76 48.26,32.48 47.65,29.98 47.62,29.98 47.5,29.85 v2(47.49,29.85) ; v1(46.67,18.35) 46.67,18.28 46.53,18.13 CN17.17
LCD_PSRAM_D2: length 55
  TOP w0.127: U10.C6 47.11,29.49 47.45,29.16 v2(47.47,29.16) ; U8.B12 38.42,50.38 v2(38.74,50.06)
  L4_SIG w0.102: v2(47.47,29.16) 47.55,29.08 47.55,28.47 47.68,28.35 48.79,28.35 48.92,28.22 48.92,26.77 49.33,26.37 49.33,24.76 48.92,24.35 48.92,22.07 49.05,21.95 49.96,21.95 50.09,21.82 50.09,21.59 49.96,21.46 49.56,21.46 49.43,21.34 49.43,21.08 49.56,20.95 49.91,20.95 50.04,20.83 50.04,20.57 49.91,20.45 47.19,20.45 47.07,20.32 47.07,20.09 47.19,19.96 48.59,19.96 48.72,19.84 48.72,19.58 48.59,19.46 46.99,19.46 46.24,18.71 46.24,17.93 46.37,17.81 48.18,17.81 48.31,17.68 48.31,17.5 48.18,17.37 46.51,17.37 46.38,17.25 46.38,16.22 v1(46.16,16)
  BOTTOM w0.127: CN17.16 46.23,15.81 46.16,15.88 v1(46.16,16) ; v2(38.74,50.06) 38.31,49.46 38.13,48.95 38.13,47.75 39.01,46.86 39.69,46.43 40.35,45.81 41.33,44.48 41.4,44.38 42.85,41.43 42.85,41.43 42.85,41.03 43.18,40.7 43.85,40.7 48.64,35.92 48.64,33.12 48.42,31.92 47.91,29.8 47.76,29.53 v2(47.47,29.16)
LCD_PSRAM_D3: length 54.9
  TOP w0.102: 46.96,28.96 46.74,29.34 46.74,29.59 U10.D5
  TOP w0.127: U8.C12 38.73,49.41 v2(38.74,49.41) ; 46.96,28.96 v2(47.02,28.85)
  L4_SIG w0.102: v2(47.02,28.85) 46.89,28.73 46.89,28.14 47.02,28.02 48.49,28.02 48.62,27.89 48.62,27.66 48.51,27.56 47.01,27.56 46.89,27.44 46.89,27.27 47.01,27.15 48.51,27.15 48.62,27.05 48.62,26.04 48.49,25.91 47.17,25.91 47.04,25.78 47.04,24.87 47.17,24.74 48.46,24.74 48.59,24.61 48.59,21.77 48.46,21.64 46.89,21.64 46.76,21.51 46.76,21.36 46.89,21.23 48.98,21.23 49.1,21.12 49.1,20.95 48.98,20.83 46.89,20.83 46.76,20.7 46.76,19.66 45.94,18.83 45.94,16.75 v1(45.95,16.74)
  BOTTOM w0.127: v2(47.02,28.85) 47.31,28.78 47.52,28.78 47.74,28.84 47.85,28.96 47.92,29.17 47.99,29.32 48.24,29.76 48.77,31.93 49.02,33.27 49.02,36.09 44.54,40.58 43.93,41.38 42.69,42.9 42.25,43.67 41.55,44.74 40.67,45.95 40.53,46.09 39.89,46.64 39.19,47.04 38.35,47.88 38.35,48.85 v2(38.74,49.41) ; v1(45.95,16.74) 45.93,16.76 CN17.15
LCD_PSRAM_D4: length 52.6
  TOP w0.127: U8.R8 35.81,40.16 35.94,40.03 36.09,40.03 36.22,40.16 v2(36.22,40.23) ; v2(45.28,29.86) 45.28,29.93 U10.E5
  L4_SIG w0.102: v2(45.28,29.86) 46.43,29.86 46.56,29.73 46.56,26.9 46.69,26.77 48.18,26.77 48.31,26.64 48.31,26.34 48.18,26.21 46.74,26.21 46.61,26.09 46.61,24.49 46.74,24.36 48.13,24.36 48.26,24.23 48.26,24.03 48.16,23.93 47.29,23.93 47.17,23.81 47.17,23.64 47.29,23.52 48.16,23.52 48.26,23.42 48.26,23.22 48.16,23.11 46.6,23.11 46.48,22.99 46.48,22.83 46.6,22.71 48.16,22.71 48.26,22.61 48.26,22.4 48.16,22.3 46.58,22.3 46.46,22.17 46.46,19.79 45.52,18.85 v1(45.52,16)
  BOTTOM w0.127: v2(36.22,40.23) 36.4,40.23 36.5,40.13 36.5,38.96 36.4,38.86 36.4,37.47 36.55,37.31 37.36,37.31 37.49,37.44 37.49,37.9 37.62,38.02 38.07,38.02 38.39,38.02 39,37.41 39.84,37.41 40.5,36.75 40.91,36.75 42.55,35.11 42.55,33.99 42.55,33.99 42.77,33.76 42.77,33.76 42.93,33.61 42.93,33.61 43.27,33.26 43.86,33.26 44.07,33.05 44.07,33.04 44.07,33.04 44.07,32.84 44.2,32.72 44.53,32.72 44.65,32.59 44.65,32.28 44.53,32.16 44.17,32.16 44.04,32.03 44.04,31.78 44.17,31.65 45.47,31.65 45.59,31.52 45.59,31.24 45.47,31.11 44.95,31.11 44.82,30.99 44.82,29.57 44.95,29.44 45.15,29.44 45.28,29.57 v2(45.28,29.86) ; CN17.14 45.63,15.89 v1(45.52,16)
LCD_PSRAM_D5: length 52.5
  TOP w0.127: v2(36.11,39.62) 36.11,39.47 35.98,39.34 35.56,39.34 35.43,39.47 35.43,40.92 35.47,40.96 35.47,41.71 35.48,41.72 35.48,42.25 U8.P8 ; U10.F5 44.81,30.24 v2(44.45,30.61)
  L4_SIG w0.102: v2(44.45,30.61) 44.45,30.86 44.58,30.99 48.16,30.99 48.29,30.86 48.29,30.35 48.16,30.23 45.03,30.23 44.91,30.1 44.91,29.58 45.03,29.45 46.13,29.45 46.25,29.33 46.25,24.59 46.13,24.46 45.39,24.46 45.26,24.33 45.26,24.08 45.39,23.95 46.74,23.95 46.86,23.83 46.86,23.65 46.74,23.52 46.25,23.52 46.13,23.39 46.13,21.34 46,21.21 45.39,21.21 45.29,21.11 45.29,20.9 45.39,20.8 45.97,20.8 46.1,20.68 46.1,20.47 45.97,20.35 45.34,20.35 45.21,20.22 45.21,19.99 45.34,19.86 45.64,19.86 45.77,19.74 45.77,19.53 45.64,19.41 45.34,19.41 45.21,19.28 45.21,18.49 45.09,18.36 v1(44.95,18.36)
  BOTTOM w0.127: v2(36.11,39.62) 36.02,39.54 36.02,37.22 36.31,36.93 37.74,36.93 37.87,37.06 37.87,37.52 38,37.64 38.23,37.64 38.35,37.52 38.35,36.2 38.48,36.07 38.81,36.07 38.94,36.2 38.94,36.91 39.07,37.03 39.66,37.03 40.32,36.37 40.75,36.37 42.16,34.96 42.16,33.83 43.69,32.31 43.69,31.5 43.81,31.37 44.25,31.37 44.37,31.24 44.37,31.09 44.25,30.96 43.84,30.96 43.71,30.84 43.71,30.4 43.84,30.28 44.32,30.28 44.45,30.4 v2(44.45,30.61) ; v1(44.95,18.36) 45.33,17.98 CN17.13
LCD_PSRAM_D6: length 49.4
  TOP w0.127: v2(44.3,29.04) 44.3,27.05 44.42,26.92 44.65,26.92 44.78,27.05 44.78,28.27 44.7,28.35 44.7,29.35 U10.F6 ; v2(36.2,41.43) 36.15,41.48 36.15,42.26 U8.P9
  L4_SIG w0.102: v1(45.09,16.64) 45.19,16.74 45.19,17.81 45.06,17.93 43.94,17.93 43.48,18.39 43.48,20.85 43.59,20.95 44.55,20.95 44.65,21.06 44.65,21.26 44.55,21.36 43.59,21.36 43.48,21.46 43.48,21.67 43.59,21.77 44.55,21.77 44.65,21.87 44.65,22.07 44.55,22.17 43.59,22.17 43.48,22.28 43.48,22.48 43.59,22.58 44.55,22.58 44.65,22.68 44.65,22.89 44.55,22.99 43.59,22.99 43.48,23.09 43.48,23.32 43.61,23.44 44.53,23.44 44.65,23.57 44.65,27.56 44.58,27.64 44.35,27.64 44.22,27.76 44.22,27.97 44.35,28.09 44.58,28.09 44.7,28.22 44.7,28.4 44.58,28.52 44.35,28.52 44.22,28.65 44.22,28.97 v2(44.3,29.04)
  BOTTOM w0.127: v2(44.3,29.04) 44.25,28.99 43.31,28.99 43.18,29.12 43.18,31.74 41.31,33.6 40.97,33.6 40.06,34.52 39.17,34.52 38.64,35.05 38.32,35.05 38.05,35.05 36.94,36.17 35.99,36.17 35.26,36.91 35.26,40.42 35.83,40.99 35.83,41.02 36.2,41.39 v2(36.2,41.43) ; CN17.12 45.03,16.17 45.09,16.23 v1(45.09,16.64)
LCD_PSRAM_D7: length 54.1
  TOP w0.127: U10.G6 44.45,29.84 v2(44.45,29.89) ; v2(36.2,40.87) 36.57,41.24 36.57,41.83 U8.R9
  L4_SIG w0.102: v1(44.25,18.36) 43.94,18.36 43.81,18.49 43.81,18.69 43.94,18.82 44.7,18.82 44.83,18.95 44.83,19.18 44.7,19.3 43.94,19.3 43.81,19.43 43.81,19.61 43.94,19.74 44.73,19.74 44.86,19.86 44.86,20.04 44.73,20.17 43.92,20.17 43.79,20.29 43.79,20.47 43.92,20.6 44.83,20.6 44.96,20.73 44.96,20.93 44.96,21.18 44.96,21.18 44.96,21.51 45.06,21.62 45.65,21.62 45.77,21.73 45.77,21.9 45.65,22.02 45.06,22.02 44.96,22.12 44.96,22.33 45.06,22.43 45.65,22.43 45.77,22.55 45.77,22.72 45.65,22.83 45.06,22.83 44.96,22.94 44.96,23.14 45.06,23.24 45.63,23.24 45.75,23.36 45.75,23.53 45.63,23.65 45.06,23.65 44.96,23.75 44.96,24.77 45.06,24.87 45.83,24.87 45.95,24.99 45.95,25.15 45.83,25.27 45.11,25.27 44.98,25.4 44.98,26.39 45.11,26.52 45.83,26.52 45.95,26.64 45.95,26.8 45.83,26.92 45.13,26.92 45.01,27.04 45.01,27.21 45.13,27.33 45.83,27.33 45.95,27.45 45.95,27.62 45.83,27.74 45.08,27.74 44.96,27.86 44.96,28.02 45.08,28.14 45.8,28.14 45.92,28.27 45.92,28.55 45.8,28.68 44.93,28.68 44.7,28.91 44.7,29.34 44.45,29.59 v2(44.45,29.89)
  BOTTOM w0.127: v2(44.45,29.89) 44.12,29.89 43.99,29.76 43.99,29.44 43.87,29.31 43.59,29.31 43.46,29.44 43.46,32 41.78,33.68 41.78,33.99 41.78,33.99 41.78,34.77 41.66,34.9 41.43,34.9 41.3,34.77 41.3,34.34 41.17,34.21 40.95,34.21 40.82,34.34 40.82,35.71 40.69,35.84 40.49,35.84 40.36,35.71 40.36,35.05 40.23,34.92 40.03,34.92 39.9,35.05 39.9,36.25 39.76,36.4 39.47,36.4 39.34,36.27 39.34,35.43 39.22,35.31 38.92,35.31 38.76,35.47 38.76,35.56 38.63,35.69 38.1,35.69 37.97,35.81 37.97,36.42 37.85,36.55 36.15,36.55 35.64,37.06 35.64,40.21 36.2,40.77 v2(36.2,40.87) ; CN17.11 44.73,17.88 v1(44.25,18.36)
LCD_PSRAM_D8: length 52.5
  TOP w0.127: v2(47.87,34.48) 48.02,34.48 48.73,35.19 48.91,35.19 49.07,35.03 49.07,34.85 47.85,33.63 U10.B1 ; v2(37.66,39.73) 37.66,39.58 37.38,39.31 36.8,39.31 36.68,39.43 36.68,41.03 36.8,41.15 36.8,42.26 U8.P10
  L4_SIG w0.102: v2(47.87,34.48) 47.87,34.25 50.7,31.42 50.7,28.83 51.1,28.42 51.1,28.42 51.33,28.2 51.33,28.2 51.36,28.17 51.36,19.61 50.9,19.15 50.75,19 50.75,18.19 46.4,13.84 v1(44.26,13.84)
  BOTTOM w0.127: CN17.10 44.43,14.01 v1(44.26,13.84) ; v2(37.66,39.73) 37.66,39.75 37.78,39.88 38.29,39.88 38.6,39.57 39.75,39.57 39.98,39.34 39.98,38.69 40.07,38.6 40.27,38.6 40.98,37.9 41.85,37.9 42.42,37.33 42.42,36.86 43.69,35.59 43.69,34.51 43.69,34.51 43.69,34.45 44.38,33.76 46.12,33.76 46.25,33.63 46.25,32.54 46.38,32.41 46.98,32.41 47.1,32.54 47.1,33.09 47.87,33.85 v2(47.87,34.48)
LCD_PSRAM_D9: length 48.4
  TOP w0.127: U8.R10 37.03,41.84 37.03,40.96 37.06,40.92 37.06,40.41 37.21,40.26 v2(37.66,40.26) ; v2(46.71,34.39) 46.71,34.08 46.83,33.96 47,33.96 47.12,34.08 47.12,34.85 47.55,35.28 47.55,36.07 47.68,36.2 47.88,36.2 48.01,36.07 48.01,35.03 47.88,34.9 47.7,34.9 47.47,34.67 47.47,33.37 47.35,33.24 U10.C1
  L4_SIG w0.102: v2(46.71,34.39) 46.18,34.39 44.73,32.94 44.73,32.13 43.61,31.01 43.61,27.48 43.97,27.13 43.97,25.12 43.84,24.99 42.98,24.99 42.85,24.87 42.85,18.03 43.76,17.12 43.76,16.33 43.11,15.67 43.1,15.67 v1(42.9,15.47)
  BOTTOM w0.127: v2(46.71,34.39) 46.81,34.49 46.96,34.49 47.09,34.37 47.09,34.11 46.96,33.99 46.43,33.99 46.38,34.04 44.64,34.04 44.07,34.61 44.07,34.67 44.07,34.67 44.07,35.75 42.8,37.02 42.8,37.48 42.01,38.28 41.14,38.28 40.36,39.05 40.36,39.55 39.52,40.4 38.98,40.4 38.87,40.28 37.68,40.28 v2(37.66,40.26) ; v1(42.9,15.47) 42.95,15.47 43.92,16.43 43.92,17.02 44.13,17.23 CN17.9
LCD_PSRAM_D10: length 51.9
  TOP w0.127: v2(37.44,42.91) U8.N11 ; v2(47.47,32.86) 47.46,32.86 U10.C2
  L4_SIG w0.102: v1(44.42,15.72) 44.42,15.29 44.6,15.11 47.24,15.11 49.75,17.61 49.75,19.33 49.87,19.46 50.77,19.46 51.05,19.74 51.05,25.3 50.93,25.43 50.55,25.43 50.42,25.55 50.42,26.72 50.55,26.84 50.95,26.84 51.05,26.95 51.05,27.15 50.95,27.25 49.99,27.25 49.89,27.35 49.89,28.19 50.01,28.32 50.27,28.32 50.39,28.45 50.39,31.29 48.83,32.86 v2(47.47,32.86)
  BOTTOM w0.127: CN17.8 43.83,15.15 44.4,15.72 v1(44.42,15.72) ; v2(37.44,42.91) 37.44,43.08 37.57,43.21 37.95,43.21 38.07,43.08 38.07,42.6 37.95,42.47 36.93,42.47 36.8,42.34 36.8,40.97 36.88,40.89 36.88,39.33 37.78,38.43 37.79,38.43 38.53,38.43 39.16,37.8 40,37.8 40.66,37.13 41.06,37.13 42.93,35.27 42.93,34.2 42.93,34.2 42.93,34.14 43.55,33.52 43.93,33.52 44.35,33.1 44.75,33.1 44.84,33.02 44.84,32.74 45.06,32.51 45.06,32.13 45.19,32 47.73,32 47.85,32.13 47.85,32.73 47.73,32.86 v2(47.47,32.86)
LCD_PSRAM_D11: length 52.6
  TOP w0.127: U8.P11 37.43,42.25 37.43,41.8 37.25,41.62 37.25,41.05 37.51,40.79 v2(37.65,40.79) ; U10.D2 46.71,32.85 v2(46.74,32.85)
  L4_SIG w0.102: v2(46.74,32.85) 46.74,32.9 47.14,33.31 47.14,34.54 46.86,34.82 46.18,34.82 44.35,32.99 44.35,32.26 43.31,31.22 43.31,29.57 43.18,29.44 42.72,29.44 42.6,29.31 42.6,27.25 42.72,27.13 43.54,27.13 43.66,27 43.66,26.37 43.54,26.24 42.77,26.24 42.65,26.11 42.65,25.91 42.77,25.78 43.51,25.78 43.64,25.65 43.64,25.44 43.52,25.32 42.67,25.32 42.55,25.2 42.55,17.86 43.38,17.02 43.38,16.56 v1(42.93,16.1)
  BOTTOM w0.127: v2(37.65,40.79) 37.77,40.67 39.48,40.67 39.76,40.94 39.76,41.59 39.88,41.72 40.21,41.72 40.31,41.62 40.31,40.68 40.32,40.68 40.32,40.29 40.94,39.67 40.94,39.01 41.29,38.66 42.27,38.66 42.41,38.8 42.96,38.8 43.18,38.58 43.18,37.17 44.45,35.9 44.45,34.77 44.8,34.42 46.2,34.42 46.68,34.9 46.77,34.9 47.12,34.9 47.24,35.03 47.24,35.38 47.49,35.62 47.67,35.62 47.8,35.49 47.8,34.97 47.47,34.65 47.47,33.88 46.74,33.14 v2(46.74,32.85) ; CN17.7 43.53,16.65 42.98,16.1 v1(42.93,16.1)
